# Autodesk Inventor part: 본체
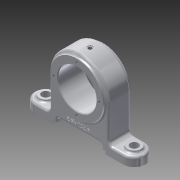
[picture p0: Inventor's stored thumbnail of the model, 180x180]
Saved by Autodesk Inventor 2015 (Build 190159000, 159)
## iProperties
Created: 2019-05
Part Number: 본체
Material: 알루미늄 6061
Document SubType Name: Modeling
Designer: now
Density: 2.7 g/cm^3
Appearance: 알루미늄 - 평지
Mass: 454.998 g
Surface Area: 321.963 cm^2
Volume: 168.518 cm^3
Author: now
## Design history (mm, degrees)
sketch "스케치2"
  geometry: L1 (75, -15)-(-75, -15); L2 (-75, -15)-(-75, 15); L3 (-75, 15)-(75, 15); L4 (75, 15)-(75, -15); L5 (75, -15)-(-75, 15); L6 (-75, -15)-(75, 15); 1 further point
  constraints: 12 end point, 2 midpoint, 2 parallel, 1 horizontal, 1 perpendicular
  dimensions: "d0" = 150 distance of L1.start L1.end; "d1" = 30 distance of L1.end L2.end
extrude "돌출1" new body sketch "스케치2" distance "d2" = 12; taper "d3" = 0 deg
sketch "스케치3"
  geometry: C1 r 9 at (-60, 0); C2 r 9 at (60, 0); 1 further point
  constraints: 2 centre point, 2 horizontal alignment
  dimensions: "d4" = 18 diameter of C1; "d5" = 18 diameter of C2; "d6" = 120 distance of C2.centre C1.centre; "d7" = 60 distance of C1.centre point (0, 0)
extrude "돌출2" join sketch "스케치3" distance "d8" = 3; taper "d9" = 0 deg
fillet "모깎기1" dims "d10" = 15
sketch "스케치5"
  geometry: L1 (-69, 12)-(-69, 15) reference; L2 (-69, 15)-(-51, 15) reference; L3 (-51, 15)-(-51, 12) reference; L4 (-51, 12)-(51, 12) reference; L5 (51, 12)-(51, 15) reference; L6 (51, 15)-(69, 15) reference; L7 (69, 15)-(69, 12) reference; L8 (69, 12)-(75, 12) reference; L9 (75, 12)-(75, 0) reference; L10 (75, 0)-(-75, 0) reference; L11 (-75, 0)-(-75, 12) reference; L12 (-75, 12)-(-69, 12) reference; C1 r 40 at (0, 60); 2 further points
  constraints: 1 centre point, 1 midpoint, 1 vertical alignment
  dimensions: "d11" = 80 diameter of C1; "d12" = 60 distance from line of L10 C1.centre
extrude "돌출3" join sketch "스케치5" stored distance "d13" = 30; taper "d14" = 0 deg
sketch "스케치6"
  geometry: L1 (-60, -15)-(60, -15) reference; L2 (-40, 15)-(40, 15); L3 (40, 15)-(40, -15); L4 (40, -15)-(-40, -15); L5 (-40, -15)-(-40, 15); L6 (-40, 15)-(40, -15); L7 (40, 15)-(-40, -15); 1 further point
  constraints: 12 end point, 2 midpoint, 2 parallel, 1 horizontal, 1 perpendicular, 1 point on line
  dimensions: "d15" = 80 distance between parallel lines of L5 L3
extrude "돌출4" join sketch "스케치6" stored distance "d16" = 0; taper "d17" = 0 deg
sketch "스케치7"
  geometry: L1 (120, 0)-(0, 0) reference; L2 (96, 4)-(24, 4); L3 (24, 4)-(24, 0); L4 (24, 0)-(96, 0); L5 (96, 0)-(96, 4); 2 further points
  constraints: 8 end point, 2 midpoint, 2 parallel, 1 horizontal, 1 perpendicular
  dimensions: "d18" = 72 distance between parallel lines of L5 L3; "d19" = 4 distance between parallel lines of L1 L2
extrude "돌출5" cut sketch "스케치7" stored distance "d20" = 36; taper "d21" = 0 deg
sketch "스케치8"
  geometry: L1 (-96, 4)-(-24, 4) reference; L2 (-90, 10)-(-30, 10); L3 (-30, 10)-(-30, 4); L4 (-30, 4)-(-90, 4); L5 (-90, 4)-(-90, 10); 2 further points
  constraints: 8 end point, 2 midpoint, 2 parallel, 1 horizontal, 1 perpendicular
  dimensions: "d22" = 6 distance between parallel lines of L4 L2; "d23" = 60 distance between parallel lines of L3 L5
extrude "돌출6" cut sketch "스케치8" stored distance "d24" = 36; taper "d25" = 0 deg
sketch "스케치10"
  geometry: C1 r 26 at (-60, 60); A1 r 40 centre (-60, 60) between (-20, 60) and (-100, 60) reference; 1 further point
  constraints: 1 centre point, 1 coincident
  dimensions: "d26" = 52 diameter of C1
extrude "돌출7" cut sketch "스케치10" stored distance "d27" = 36; taper "d28" = 0 deg
sketch "스케치11"
  geometry: C1 r 26 at (-60, 60) reference; C2 r 36 at (-60, 60); A1 r 40 centre (-60, 60) between (-20, 60) and (-100, 60) reference; 1 further point
  constraints: 1 centre point, 1 coincident
  dimensions: "d29" = 72 diameter of C2
extrude "돌출8" join sketch "스케치11" distance "d30" = 3; taper "d31" = 0 deg
sketch "스케치12"
  geometry: C1 r 26 at (0, 0) reference; 2 further points
  constraints: 1 vertical alignment
  dimensions: "d32" = 31 distance of point (0, 31) C1.centre
hole "구멍1" sketch "스케치12" at (0, 31) diameter "d33" = 3.242; stored, may be unused: countersink angle "d37" = 90 deg, drill point angle "d39" = 118 deg; dims "d34" = 6, "d35" = 4, "d36" = 2, "d38" = 8
node "작업 평면1"
sketch "스케치13"
  geometry: 1 further point
hole "구멍2" sketch "스케치13" at (0, 0) diameter "d44" = 4.917; stored, may be unused: countersink angle "d48" = 90 deg, drill point angle "d50" = 118 deg; dims "d45" = 8, "d46" = 7, "d47" = 1, "d49" = 10
sketch "스케치14"
  geometry: C1 r 3.5 at (0, 0) reference
hole "구멍3" sketch "스케치14" at (0, 0) diameter "d51" = 2; stored, may be unused: countersink angle "d55" = 90 deg, drill point angle "d57" = 118 deg; dims "d52" = 8, "d53" = 7, "d54" = 1, "d56" = 30
hole "구멍4" diameter "d60" = 11; stored, may be unused: countersink angle "d64" = 90 deg, drill point angle "d66" = 118 deg; dims "d58" = 10, "d59" = 10, "d61" = 8, "d62" = 7, "d63" = 1, "d65" = 30
chamfer "모따기1" distance "d67" = 1; stored, may be unused: second distance "d68" = 2, angle "d69" = 45 deg
fillet "모깎기2" dims "d70" = 6
fillet "모깎기3" dims "d71" = 3
fillet "모깎기4" dims "d72" = 3
fillet "모깎기5" dims "d73" = 3
sketch "스케치15"
  geometry: C1 r 1.5 at (0, -26); A1 r 36 centre (0, 0) between (-34.154, 11.38) and (34.154, 11.38) reference; 2 further points
  constraints: 2 vertical alignment, 1 centre point, 1 other
  dimensions: "d74" = 3 diameter of C1
extrude "돌출9" cut sketch "스케치15" stored distance "d75" = 3; taper "d76" = 0 deg
sketch "스케치16"
  geometry: L1 (-63, 10)-(-9, 10) reference; A1 r 3 centre (-9, 7) between (-6, 7) and (-9, 10) reference; 3 further points
  constraints: 1 other
  dimensions: "d77" = 7 distance from line of point (-36, 17) L1; "d78" = 30 horizontal distance of point (-6, 4) point (-36, 17)
feature "엠보싱1" sketch "스케치16" dims "d0" = 150, "d1" = 30, "d79" = 0.5, "d80" = 0
node "솔리드1"
mirror "대칭1"
pattern_circular "원형 패턴1" dims angle "d41" = 360 deg
mirror "대칭2"
mirror "대칭3"
node "절단 모서리 투영1"
